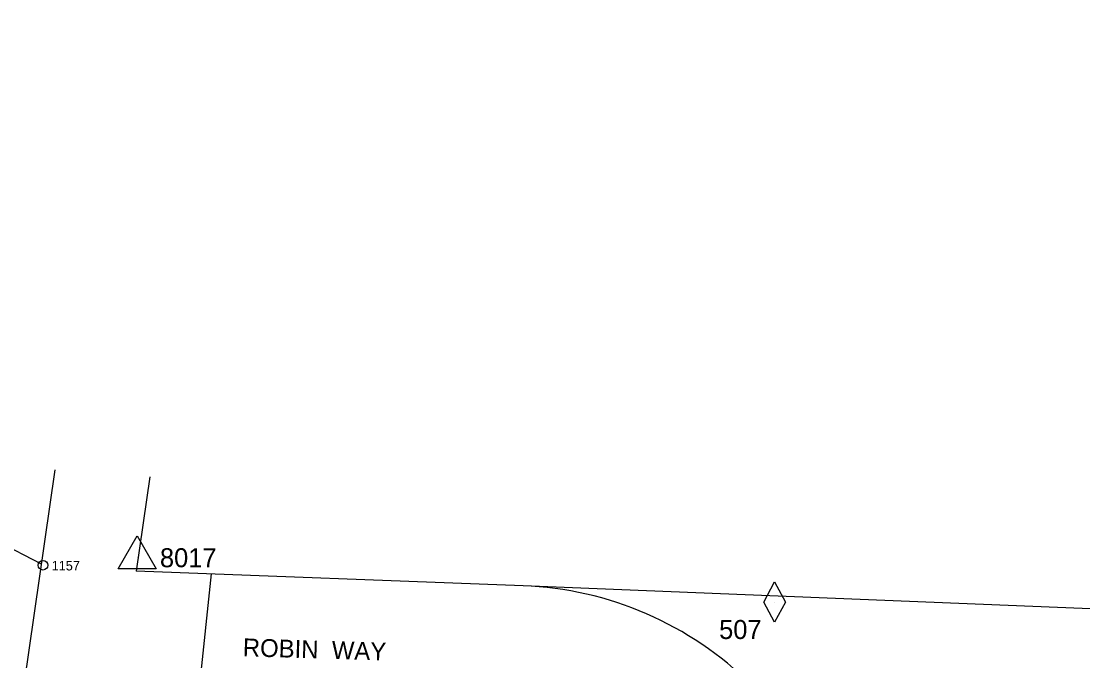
# Model space of a CAD drawing. Extents: x 7581380 to 7602708, y 543740 to 556109.
# Drawn here: x 7587436 to 7587995, y 550907 to 551243 of the extents above; entities that cross this region are included whole.
import ezdxf

# ---------------------------------------------------------------- set-up
doc = ezdxf.new("R2010")
doc.units = 0
for name, color, linetype in [('E_RDWY_ROAD_NameTx', 7, 'Continuous'), ('E_SURV_BNDRY_CROW', 7, 'Continuous'), ('E_SURV_BNDRY_Property', 7, 'Continuous'), ('E_SURV_MON_FdMon', 7, 'Continuous'), ('E_SURV_MON_FdMonTx', 7, 'Continuous'), ('E_SURV_NTW_SetNtwPt', 7, 'Continuous'), ('E_SURV_NTW_SetNtwPtTx', 7, 'Continuous'), ('E_SURV_NTW_SetStrategicPt', 7, 'Continuous'), ('E_SURV_NTW_SetStrategicPtTx', 7, 'Continuous')]:
    doc.layers.add(name, color=color, linetype=linetype)

msp = doc.modelspace()

# ---------------------------------------------------------------- linework, layer by layer
at = {"layer": 'E_SURV_BNDRY_CROW'}
for p, q in [((7587454.09, 551007.61), (7587384.32, 550524.19)), ((7587504.08, 551003.88), (7587496.92, 550954.32)), ((7587700.37, 550946.62), (7587496.92, 550954.32))]:
    msp.add_line(p, q, dxfattribs=at)
msp.add_arc((7587693.57, 550766.75), 180, 45.2227, 87.8328, dxfattribs=at)
at = {"layer": 'E_SURV_BNDRY_Property'}
for p, q in [((7586220, 551589.9), (7587446.95, 550958.12)), ((7587528.11, 550873.08), (7587536.53, 550952.81)), ((7588032.47, 550933.08), (7587700.37, 550946.62))]:
    msp.add_line(p, q, dxfattribs=at)
at = {"layer": 'E_SURV_MON_FdMon'}
msp.add_circle((7587447.93, 550957.37), 2.5, dxfattribs=at)
at = {"layer": 'E_SURV_NTW_SetNtwPt'}
for p, q in [((7587487.42, 550955.56), (7587497.42, 550972.88)), ((7587497.42, 550972.88), (7587507.42, 550955.56)), ((7587497.42, 550961.33), (7587497.42, 550961.33)), ((7587507.42, 550955.56), (7587487.42, 550955.56))]:
    msp.add_line(p, q, dxfattribs=at)
at = {"layer": 'E_SURV_NTW_SetStrategicPt'}
for p, q in [((7587826.96, 550937.97), (7587832.63, 550948.58)), ((7587832.63, 550948.58), (7587838.3, 550937.97)), ((7587832.63, 550948.58), (7587832.63, 550948.58)), ((7587832.63, 550927.37), (7587826.96, 550937.97)), ((7587832.63, 550937.97), (7587832.63, 550937.97)), ((7587838.3, 550937.97), (7587832.63, 550927.37))]:
    msp.add_line(p, q, dxfattribs=at)

# ---------------------------------------------------------------- texts
at = {"layer": 'E_RDWY_ROAD_NameTx'}
msp.add_text('ROBIN  WAY', height=9.4, rotation=358.2706, dxfattribs=at).set_placement((7587552.88, 550909.56))
at = {"layer": 'E_SURV_MON_FdMonTx'}
msp.add_text('1157', height=5, dxfattribs=at).set_placement((7587452.46, 550954.64))
at = {"layer": 'E_SURV_NTW_SetNtwPtTx'}
msp.add_text('8017', height=10, dxfattribs=at).set_placement((7587509.42, 550956.33))
at = {"layer": 'E_SURV_NTW_SetStrategicPtTx'}
msp.add_text('507', height=10, dxfattribs=at).set_placement((7587803.48, 550918.6))

doc.saveas('drawing.dxf')
